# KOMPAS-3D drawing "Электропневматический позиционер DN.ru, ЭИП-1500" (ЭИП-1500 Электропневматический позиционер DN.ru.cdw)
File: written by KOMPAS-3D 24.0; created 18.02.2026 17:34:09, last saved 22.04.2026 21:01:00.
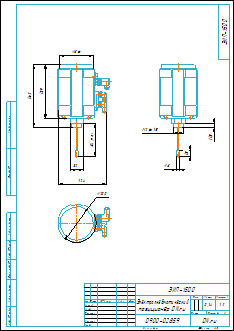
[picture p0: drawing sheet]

Document properties: Автор: R2D2; Форматы листов документа: A3; Полное имя файла: ЭИП-1500 Электропневматический позиционер DN.ru.m3d; Масса: 0.14; Наименование: Электропневматический позиционер DN.ru; Количество листов документа: 1; Примечание: D900-02859

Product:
- Part/product: Электропневматический позиционер DN.ru  | designation ЭИП-1500
    Масса: 0.14
    Раздел спецификации: Прочие изделия
    Примечание: D900-02859

Views: Проекционный вид 2
Referenced files in E:\Работа\Зайцев\Аксессуары для пневмоприводов\Электропневматические позиционеры DN.ru\ЭИП Электропневматический позиционер DN.ru\ЭИП-1500 Электропневматический позиционер DN.ru\5-25\: ЭИП-1500 Электропневматический позиционер DN.ru.m3d
Referenced files in E:\Работа\Зайцев\Для компаса\: чертеж DN.ru А3.cdt
Referenced files in E:\Работа\Зайцев\Аксессуары для пневмоприводов\Электропневматические позиционеры DN.ru\ЭИП Электропневматический позиционер DN.ru\ЭИП-1500 Электропневматический позиционер DN.ru\25-50\: ЭИП-1500 Электропневматический позиционер DN.ru.m3d
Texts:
  ЭИП-1500
  чертеж DN.ru А3.cdt
  Электропневматический
  позиционер DN.ru
  Электропневматический позиционер DN.ru
  ЭИП-1500 Электропневматический позиционер DN.ru
Dimensions and other numbers on the sheet: 0; 3; 4; 15; 11,5; 8; 26; 1:2; 1; 2; 0,14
